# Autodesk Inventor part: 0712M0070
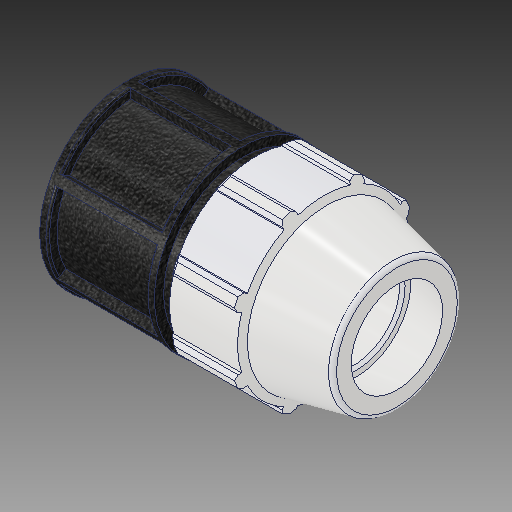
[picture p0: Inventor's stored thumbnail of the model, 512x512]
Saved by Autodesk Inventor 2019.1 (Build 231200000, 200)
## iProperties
Created: 2017-02
Part Number: 0712M0070
Material: PVC-Piping
Description: PLASSON END PLUG 3/4''
Document SubType Name: Modeling
Designer: KIM
Mass: 92.6774 g
Surface Area: 199.44 cm^2
Volume: 66.1981 cm^3
Density: 1.4 g/cm^3
Appearance: PTFE
Author: Кирилл
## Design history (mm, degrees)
derived "0712M0.ipt"
feature "Solid1::0712M0.ipt"
tag "TaggingFeature1"
body "Solid1"
other parameters: "d2" = 26.6, "d4" = 11.72029, "d5" = 20.5105, "d7" = 54.102, "d8" = 45.9867, "d9" = 11.72029, "d11" = 2.34406, "d12" = 45.9867, "d13" = 120 deg, "d15" = 12 deg, "d16" = 51.3969, "d18" = 1.33, "d19" = 35 deg, "d20" = 17.5 deg, "d21" = 50.31486, "d23" = 0, "d25" = 360 deg, "d27" = 1.08204, "d34" = 2.7051, "d36" = 0, "d42" = 20.5105, "d43" = 1.62306, "d46" = 0.798, "d53" = 0.532, "d55" = 360 deg, "d59" = 28.7147, "d64" = 82.042, "d66" = 5.4102, "d67" = 2.7051, "d68" = 75.946, "d70" = 45.9867, "d_" = 26.6, "E_" = 54.102, "H_" = 82.042, "l_" = 75.946
